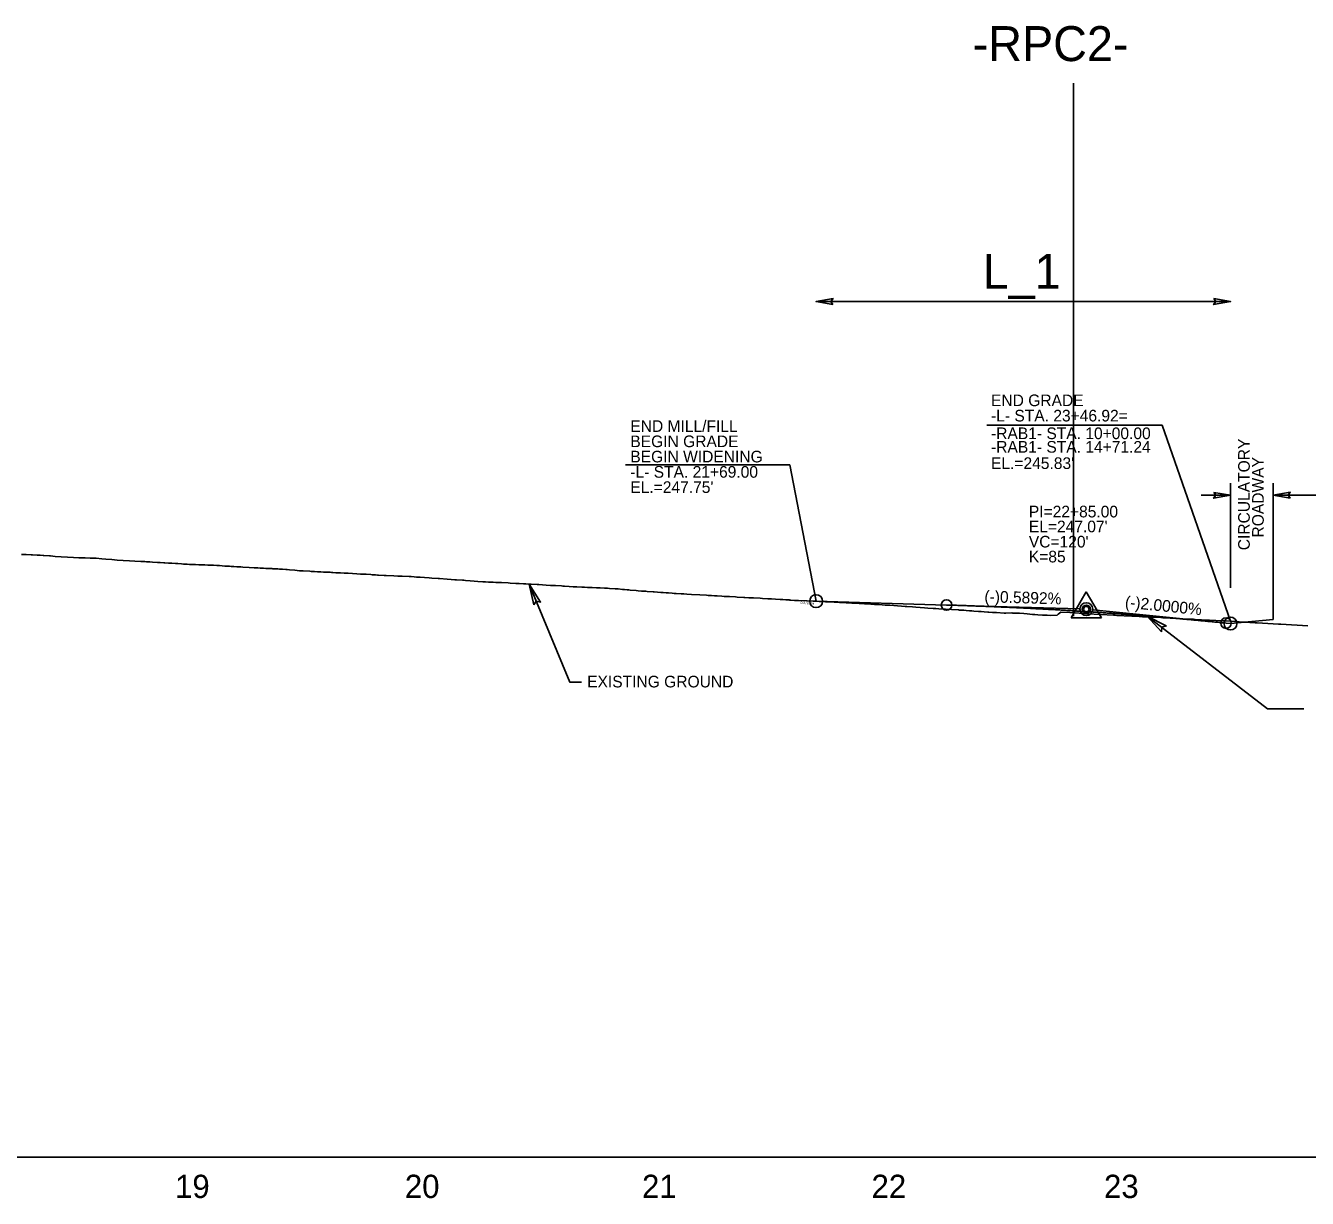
# Model space of a CAD drawing. Extents: x 2115752 to 2121174, y 562881 to 567245.
# Drawn here: x 2117526 to 2118076, y 566358 to 566862 of the extents above; entities that cross this region are included whole.
import ezdxf

# ---------------------------------------------------------------- set-up
doc = ezdxf.new("R2010")
doc.units = 0
for name, color, linetype in [('Exist Profile Cell', 7, 'Continuous'), ('Exist Vertical Profile Ground Line', 7, 'Continuous'), ('Exist Vertical Profile Horizontal Axis Label Major', 7, 'Continuous'), ('Prop PFL VPI Symbol CELL', 7, 'Continuous'), ('Prop Terminator CELL', 7, 'Continuous'), ('Prop Vertical Profile Curve Label', 7, 'Continuous'), ('Prop Vertical Profile Grade', 7, 'Continuous'), ('Prop Vertical Profile Grade Label', 7, 'Continuous'), ('Prop VPI Label', 7, 'Continuous'), ('Scratch_Level_1', 7, 'Continuous')]:
    doc.layers.add(name, color=color, linetype=linetype)

msp = doc.modelspace()

# ---------------------------------------------------------------- linework, layer by layer
at = {"layer": 'Exist Profile Cell'}
msp.add_line((2116696.3, 566375.81), (2121174.42, 566375.81), dxfattribs=at)
at = {"layer": 'Exist Vertical Profile Ground Line'}
for points in [[(2117524.02, 566634.65), (2117526.09, 566634.57), (2117528.2, 566634.49), (2117528.76, 566634.48), (2117530.8, 566634.38), (2117531.12, 566634.36), (2117532.16, 566634.29), (2117533.35, 566634.21), (2117533.68, 566634.19), (2117536.03, 566634), (2117536.56, 566633.98), (2117538.6, 566633.82), (2117541.16, 566633.67), (2117543.79, 566633.49), (2117546.4, 566633.36), (2117548.64, 566633.22), (2117551.1, 566633.13), (2117551.4, 566633.13), (2117553.62, 566633.09), (2117554.92, 566633.03), (2117556.16, 566632.98), (2117558.59, 566632.82), (2117560.27, 566632.66), (2117562.84, 566632.44), (2117565.22, 566632.21), (2117567.8, 566632.02), (2117570.49, 566631.85), (2117572.79, 566631.73), (2117575.35, 566631.64), (2117577.05, 566631.55), (2117577.72, 566631.51), (2117579.2, 566631.41), (2117580.3, 566631.35), (2117582.5, 566631.21), (2117582.82, 566631.19), (2117583.62, 566631.15), (2117585.22, 566631.05), (2117585.69, 566631.02)], [(2117585.69, 566631.02), (2117587.18, 566630.93), (2117587.72, 566630.9), (2117588.66, 566630.83), (2117590.21, 566630.74), (2117591.18, 566630.68), (2117592.71, 566630.59), (2117593.7, 566630.52), (2117595.2, 566630.43), (2117596.21, 566630.38), (2117597.7, 566630.32), (2117598.75, 566630.33), (2117600.2, 566630.2), (2117600.88, 566630.18), (2117601.55, 566630.15), (2117602.01, 566630.17), (2117602.74, 566630.14), (2117604.05, 566630.05), (2117604.97, 566630.02), (2117606.06, 566630), (2117606.55, 566629.96), (2117607.91, 566629.9), (2117609.13, 566629.82), (2117610.23, 566629.75), (2117611.38, 566629.67), (2117612.07, 566629.63), (2117613.36, 566629.54), (2117614.05, 566629.49), (2117614.48, 566629.49), (2117615.28, 566629.44), (2117616.55, 566629.34), (2117617.99, 566629.31), (2117618.32, 566629.29), (2117619.05, 566629.2), (2117621.8, 566629.1), (2117624.05, 566628.9), (2117624.94, 566628.9), (2117625.49, 566628.87), (2117626.54, 566628.78), (2117628, 566628.71), (2117628.93, 566628.66), (2117629.66, 566628.64), (2117631.03, 566628.55), (2117631.51, 566628.54), (2117631.99, 566628.49), (2117633.36, 566628.46), (2117634.12, 566628.41), (2117634.82, 566628.37), (2117636.14, 566628.25), (2117637.6, 566628.17), (2117638.13, 566628.14), (2117639.17, 566628.02), (2117641.39, 566627.84), (2117643.41, 566627.64), (2117644.73, 566627.61), (2117645.08, 566627.59), (2117647.91, 566627.41), (2117648.46, 566627.38), (2117648.89, 566627.36), (2117649.83, 566627.25), (2117651.14, 566627.22), (2117651.7, 566627.19), (2117652.62, 566627.15), (2117653.75, 566627.06), (2117654.43, 566627.05), (2117654.83, 566627.02), (2117655.69, 566627), (2117656.62, 566626.97), (2117657.16, 566626.94), (2117657.7, 566626.92), (2117658.98, 566626.81), (2117660.34, 566626.76), (2117661.09, 566626.73), (2117662.57, 566626.62), (2117664.37, 566626.56), (2117668.07, 566626.36), (2117669.66, 566626.21), (2117670.9, 566626.19), (2117671.43, 566626.15), (2117672.13, 566626.1), (2117674.09, 566625.97), (2117674.59, 566625.94), (2117676.11, 566625.83), (2117676.95, 566625.74), (2117677.42, 566625.75), (2117679.82, 566625.62), (2117680.21, 566625.57), (2117680.67, 566625.56), (2117683.89, 566625.43), (2117685.6, 566625.34), (2117687.58, 566625.32), (2117690.54, 566625.16), (2117690.96, 566625.13), (2117691.43, 566625.11), (2117692.7, 566624.99), (2117693.75, 566624.94), (2117695.3, 566624.83), (2117697.07, 566624.69), (2117699.15, 566624.55), (2117700.33, 566624.47), (2117703.03, 566624.3)], [(2117703.03, 566624.3), (2117703.57, 566624.25), (2117706.89, 566624), (2117708.62, 566623.88), (2117710.15, 566623.79), (2117710.9, 566623.74), (2117713.39, 566623.59), (2117714.02, 566623.52), (2117714.77, 566623.43), (2117716.74, 566623.24), (2117718.5, 566623.1), (2117719.99, 566623.04), (2117722.17, 566622.91), (2117723.3, 566622.82), (2117724.6, 566622.74), (2117726.28, 566622.69), (2117726.65, 566622.67), (2117727.79, 566622.63), (2117729.71, 566622.55), (2117730.24, 566622.53), (2117733.08, 566622.39), (2117733.95, 566622.35), (2117736.33, 566622.18), (2117737.82, 566622.11), (2117739.63, 566622.04), (2117740.6, 566621.95), (2117741.79, 566621.92), (2117742.98, 566621.86), (2117745.5, 566621.72), (2117746.19, 566621.69), (2117749.43, 566621.51), (2117751.29, 566621.34), (2117752.76, 566621.3), (2117753.36, 566621.26), (2117756, 566621.09), (2117756.55, 566621.06), (2117757.19, 566621.02), (2117759.27, 566620.88), (2117760.97, 566620.8), (2117762.57, 566620.71), (2117764.66, 566620.65), (2117765.85, 566620.6), (2117767.12, 566620.48), (2117769.18, 566620.44), (2117771, 566620.36), (2117772.62, 566620.29), (2117774.37, 566620.13), (2117775.67, 566620.13), (2117776.53, 566620.08), (2117778.98, 566619.93), (2117780.3, 566619.82), (2117782.2, 566619.63), (2117783.07, 566619.53), (2117784.13, 566619.47), (2117784.89, 566619.37), (2117785.5, 566619.33), (2117788.01, 566619.13), (2117788.87, 566619.06), (2117790.3, 566618.9), (2117792.13, 566618.83), (2117792.76, 566618.78), (2117795.38, 566618.59), (2117795.72, 566618.57), (2117798.6, 566618.35), (2117799.01, 566618.32), (2117799.55, 566618.29), (2117800.94, 566618.16), (2117801.92, 566618.13), (2117803.51, 566618.02), (2117804.37, 566617.93), (2117805.17, 566617.91), (2117807.34, 566617.77), (2117808.44, 566617.69), (2117809.81, 566617.58), (2117811.74, 566617.49), (2117815.3, 566617.3), (2117818.21, 566617.11), (2117819, 566617.07), (2117820.37, 566616.94), (2117821.59, 566616.92), (2117822.76, 566616.85), (2117824.85, 566616.71), (2117825.76, 566616.64), (2117826.89, 566616.6), (2117827.51, 566616.53), (2117828.05, 566616.52), (2117830.65, 566616.4), (2117831.37, 566616.35), (2117834.22, 566616.19), (2117834.7, 566616.16), (2117836.37, 566616.02), (2117838.08, 566615.99), (2117838.43, 566615.98), (2117841.2, 566615.84), (2117842.21, 566615.78), (2117844.51, 566615.63), (2117845.22, 566615.58), (2117846.14, 566615.53), (2117847.79, 566615.41), (2117849.87, 566615.3), (2117851.01, 566615.23)], [(2117851.01, 566615.23), (2117852.26, 566615.12), (2117853.67, 566615.08), (2117854.06, 566615.06), (2117854.4, 566615.04), (2117855.97, 566614.92), (2117857.78, 566614.91), (2117861.14, 566614.77), (2117861.46, 566614.76), (2117864.08, 566614.62), (2117864.65, 566614.59), (2117865.4, 566614.56), (2117866.56, 566614.47), (2117867.5, 566614.44), (2117869.27, 566614.35), (2117870.71, 566614.28), (2117872.97, 566614.16), (2117873.96, 566614.11), (2117875.39, 566614), (2117877.27, 566613.94), (2117878.12, 566613.9), (2117880.55, 566613.76), (2117880.87, 566613.74), (2117883.78, 566613.58), (2117884.15, 566613.56), (2117884.67, 566613.54), (2117886.07, 566613.43), (2117887.08, 566613.4), (2117888.74, 566613.31), (2117890.36, 566613.21), (2117892.36, 566613.1), (2117893.65, 566613), (2117894.87, 566612.89), (2117896.41, 566612.85), (2117896.99, 566612.81), (2117900.18, 566612.6), (2117901.97, 566612.4), (2117903.5, 566612.33), (2117903.83, 566612.31), (2117904.2, 566612.28), (2117906.7, 566612.08), (2117908.04, 566612), (2117909.97, 566611.87), (2117911.89, 566611.72), (2117913.27, 566611.61), (2117915.52, 566611.45), (2117916.62, 566611.38), (2117918, 566611.26), (2117919.85, 566611.18), (2117920.85, 566611.12), (2117923.43, 566610.97), (2117926.43, 566610.8), (2117926.81, 566610.77), (2117927.31, 566610.75), (2117928.67, 566610.64), (2117929.72, 566610.58), (2117931.19, 566610.48), (2117932.12, 566610.39), (2117932.97, 566610.34), (2117935.08, 566610.19), (2117936.22, 566610.11), (2117937.49, 566609.98), (2117938.98, 566609.92), (2117939.51, 566609.88), (2117940.96, 566609.75), (2117942.79, 566609.65), (2117946.01, 566609.49), (2117946.7, 566609.49), (2117949.36, 566609.51), (2117949.82, 566609.48), (2117950.38, 566609.46), (2117951.64, 566609.36), (2117952.63, 566609.36), (2117954.51, 566609.21), (2117955.9, 566609.07), (2117958.17, 566608.91), (2117959.17, 566608.83), (2117960.47, 566608.71), (2117962.49, 566608.59), (2117964.56, 566608.5), (2117966.01, 566608.44), (2117968.76, 566608.59), (2117969.2, 566608.96), (2117970.35, 566609.89), (2117974.17, 566609.65), (2117976.36, 566609.52), (2117978.17, 566609.4), (2117979.44, 566609.32), (2117980.41, 566609.24), (2117980.88, 566609.21), (2117981.88, 566609.15), (2117993.04, 566608.56), (2117993.67, 566608.53), (2117994.36, 566608.49), (2118003.94, 566607.99), (2118004.65, 566607.95), (2118005.4, 566607.91), (2118013.36, 566607.49), (2118014.11, 566607.45), (2118020.46, 566607.13), (2118021.18, 566607.1)], [(2118021.18, 566607.1), (2118021.89, 566607.06), (2118027.4, 566606.78), (2118028.09, 566606.75), (2118033.61, 566606.46), (2118034.27, 566606.42), (2118039.78, 566606.12), (2118040.39, 566606.09), (2118045.91, 566605.78), (2118047, 566605.72), (2118053.75, 566605.33), (2118054.62, 566605.28), (2118063.81, 566604.76), (2118064.39, 566604.72), (2118064.82, 566604.69), (2118076.37, 566604.03)]]:
    msp.add_lwpolyline(points, dxfattribs=at)
at = {"layer": 'Prop PFL VPI Symbol CELL'}
for p, q in [((2117981.3, 566618.63), (2117974.85, 566607.43)), ((2117981.3, 566618.63), (2117987.8, 566607.43)), ((2117974.85, 566607.43), (2117987.8, 566607.43))]:
    msp.add_line(p, q, dxfattribs=at)
for radius in [1.75, 1.2]:
    msp.add_circle((2117981.3, 566611.15), radius, dxfattribs=at)
at = {"layer": 'Prop Terminator CELL'}
for points in [[(2118036.02, 566661.29), (2118043.22, 566660.05), (2118035.98, 566658.77), (2118036.9, 566660.05)], [(2118068.81, 566658.81), (2118061.61, 566660.05), (2118068.85, 566661.33), (2118067.93, 566660.05)], [(2117744.03, 566613.01), (2117742, 566621.91), (2117746.95, 566614.17), (2117745.04, 566614.62)], [(2118013.65, 566601.47), (2118007.47, 566608.19), (2118015.61, 566603.94), (2118013.72, 566603.37)]]:
    msp.add_lwpolyline(points, close=True, dxfattribs=at)
at = {"layer": 'Prop Vertical Profile Curve Label'}
for centre in [(2117921.3, 566612.92), (2118041.3, 566605.15)]:
    msp.add_circle(centre, 2.25, dxfattribs=at)
at = {"layer": 'Prop Vertical Profile Grade'}
for p, q in [((2117865.3, 566614.57), (2117921.3, 566612.92)), ((2118041.3, 566605.15), (2118043.22, 566604.96))]:
    msp.add_line(p, q, dxfattribs=at)
msp.add_spline([(2117921.3, 566612.92), (2117923.7, 566612.84), (2117926.1, 566612.77), (2117928.5, 566612.69), (2117930.9, 566612.61), (2117933.3, 566612.52), (2117935.7, 566612.43), (2117938.1, 566612.34), (2117940.5, 566612.24), (2117942.9, 566612.14), (2117945.3, 566612.04), (2117947.7, 566611.93), (2117950.1, 566611.82), (2117952.5, 566611.71), (2117954.9, 566611.59), (2117957.3, 566611.47), (2117959.7, 566611.35), (2117962.1, 566611.22), (2117964.5, 566611.09), (2117966.9, 566610.96), (2117969.3, 566610.82), (2117971.7, 566610.68), (2117974.1, 566610.54), (2117976.5, 566610.39), (2117978.9, 566610.24), (2117981.3, 566610.09), (2117983.7, 566609.93), (2117986.1, 566609.77), (2117988.5, 566609.61), (2117990.9, 566609.44), (2117993.3, 566609.27), (2117995.7, 566609.1), (2117998.1, 566608.92), (2118000.5, 566608.74), (2118002.9, 566608.55), (2118005.3, 566608.37), (2118007.7, 566608.18), (2118010.1, 566607.98), (2118012.5, 566607.78), (2118014.9, 566607.58), (2118017.3, 566607.38), (2118019.7, 566607.17), (2118022.1, 566606.96), (2118024.5, 566606.74), (2118026.9, 566606.53), (2118029.3, 566606.31), (2118031.7, 566606.08), (2118034.1, 566605.85), (2118036.5, 566605.62), (2118038.9, 566605.39), (2118041.3, 566605.15)], degree=3, dxfattribs=at)
at = {"layer": 'Prop VPI Label'}
for p, q in [((2117938.55, 566690.13), (2118013.85, 566690.13)), ((2118043.22, 566605.93), (2118013.85, 566690.13)), ((2117783.43, 566673.14), (2117853.98, 566673.14)), ((2117865.3, 566614.57), (2117853.98, 566673.14)), ((2118043.22, 566620.34), (2118043.22, 566665.25)), ((2118061.61, 566606.68), (2118061.61, 566665.25)), ((2118030.6, 566660.05), (2118043.22, 566660.05)), ((2118061.61, 566660.05), (2118172.41, 566660.05)), ((2117921.3, 566612.92), (2117978.55, 566611.23)), ((2118041.3, 566605.15), (2117984.04, 566610.87)), ((2118061.61, 566606.68), (2118043.22, 566604.96))]:
    msp.add_line(p, q, dxfattribs=at)
for points in [[(2117764.53, 566579.78), (2117759.56, 566579.78), (2117742, 566621.91)], [(2118074.73, 566568.36), (2118059.14, 566568.36), (2118007.47, 566608.19)]]:
    msp.add_lwpolyline(points, dxfattribs=at)
for centre in [(2117865.3, 566614.57), (2117981.3, 566611.15), (2118043.22, 566604.96)]:
    msp.add_circle(centre, 2.75, dxfattribs=at)
at = {"layer": 'Scratch_Level_1'}
for p, q in [((2117975.87, 566608.19), (2117975.87, 566837.03)), ((2117865.3, 566743.23), (2118043.22, 566743.23)), ((2117865.3, 566614.57), (2117864.08, 566614.62)), ((2117891.3, 566613.15), (2117890.36, 566613.21)), ((2117896.3, 566612.85), (2117894.87, 566612.89)), ((2117966.01, 566608.44), (2117960.47, 566608.71))]:
    msp.add_line(p, q, dxfattribs=at)
for points in [[(2117872.5, 566741.99), (2117865.3, 566743.23), (2117872.54, 566744.51), (2117871.62, 566743.23)], [(2118036.02, 566744.47), (2118043.22, 566743.23), (2118035.98, 566741.95), (2118036.9, 566743.23)]]:
    msp.add_lwpolyline(points, close=True, dxfattribs=at)

# ---------------------------------------------------------------- texts
at = {"layer": 'Exist Vertical Profile Horizontal Axis Label Major'}
for s, p in [('19', (2117590.01, 566358.31)), ('20', (2117688.69, 566358.31)), ('21', (2117790.53, 566358.31)), ('22', (2117889.08, 566358.31)), ('23', (2117988.91, 566358.31))]:
    msp.add_text(s, height=10, dxfattribs=at).set_placement(p)
at = {"layer": 'Prop Vertical Profile Curve Label'}
for s, p in [("VC=120'", (2117956.63, 566637.62)), ('K=85', (2117956.63, 566631.21))]:
    msp.add_text(s, height=5, dxfattribs=at).set_placement(p)
at = {"layer": 'Prop Vertical Profile Grade Label'}
for s, rotation, p in [('(-)0.5892%', 358.3125, (2117937.49, 566614.14)), ('(-)2.0000%', 354.2894, (2117997.73, 566611.82))]:
    msp.add_text(s, height=5, rotation=rotation, dxfattribs=at).set_placement(p)
at = {"layer": 'Prop VPI Label'}
for s, p in [('END GRADE', (2117940.39, 566698.3)), ('-L- STA. 23+46.92=', (2117940.39, 566691.73)), ('END MILL/FILL', (2117785.51, 566687.25)), ('BEGIN GRADE', (2117785.51, 566680.7)), ('-RAB1- STA. 10+00.00', (2117940.39, 566684.15)), ('BEGIN WIDENING', (2117785.51, 566674.15)), ('-RAB1- STA. 14+71.24', (2117940.39, 566678.33)), ("EL.=245.83'", (2117940.39, 566671.33)), ('-L- STA. 21+69.00', (2117785.51, 566667.59)), ("EL.=247.75'", (2117785.51, 566661.04)), ('PI=22+85.00', (2117956.63, 566650.54)), ("EL=247.07'", (2117956.63, 566644.14)), ('EXISTING GROUND', (2117766.97, 566577.54))]:
    msp.add_text(s, height=5, dxfattribs=at).set_placement(p)
for s, p in [('CIRCULATORY', (2118051.5, 566636.44)), ('ROADWAY', (2118057.51, 566641.91))]:
    msp.add_text(s, height=5, rotation=90, dxfattribs=at).set_placement(p)
at = {"layer": 'Scratch_Level_1'}
for s, p in [('-RPC2-', (2117932.54, 566846.46)), ('L_1', (2117936.82, 566748.69))]:
    msp.add_text(s, height=15, dxfattribs=at).set_placement(p)
msp.add_text('-0.8787 %', height=1, rotation=357.4843, dxfattribs=at).set_placement((2117858.14, 566613.4))

doc.saveas('drawing.dxf')
